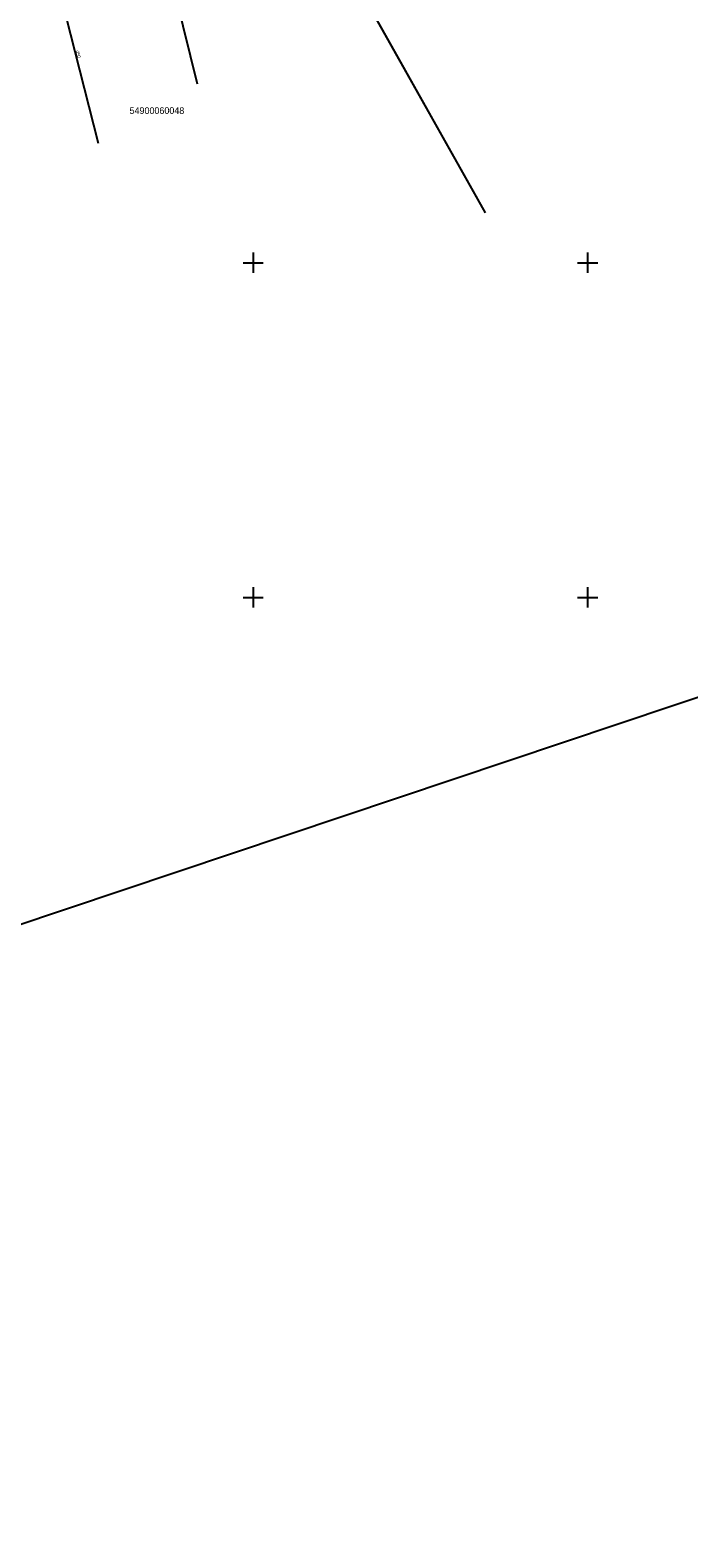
# Model space of a CAD drawing. Extents: x 469981 to 472086, y 246785 to 247785.
# Drawn here: x 471366.7 to 471465.1, y 247109.5 to 247334.7 of the extents above; entities that cross this region are included whole.
import ezdxf

# ---------------------------------------------------------------- set-up
doc = ezdxf.new("R2010")
doc.units = 0
for name, color, linetype in [('DREN_VADP_####_####_#', 7, 'Continuous'), ('DREN_VADP_####_TKST_#', 7, 'Continuous'), ('GEOD_ELEM_####_####_#', 7, 'Continuous'), ('RAMI_PLAN_####_TKST_#', 7, 'Continuous'), ('ROBZ_IERR_####_####_#', 7, 'Continuous'), ('ROBZ_UZMR_####_####_#', 7, 'Continuous'), ('ROBZ_UZMR_####_TKST_#', 7, 'Continuous')]:
    doc.layers.add(name, color=color, linetype=linetype)

msp = doc.modelspace()

# ---------------------------------------------------------------- linework, layer by layer
at = {"layer": 'DREN_VADP_####_####_#'}
for points in [[(471391.68, 247326.68), (471384.23, 247356.95)], [(471369.21, 247347.82), (471376.84, 247317.88)]]:
    msp.add_lwpolyline(points, dxfattribs=at)
at = {"layer": 'GEOD_ELEM_####_####_#'}
for p, q in [((471400, 247301.5), (471400, 247300)), ((471450, 247301.5), (471450, 247300)), ((471398.5, 247300), (471400, 247300)), ((471400, 247300), (471400, 247298.5)), ((471400, 247300), (471401.5, 247300)), ((471448.5, 247300), (471450, 247300)), ((471450, 247300), (471450, 247298.5)), ((471450, 247300), (471451.5, 247300)), ((471400, 247251.5), (471400, 247250)), ((471450, 247251.5), (471450, 247250)), ((471398.5, 247250), (471400, 247250)), ((471400, 247250), (471400, 247248.5)), ((471400, 247250), (471401.5, 247250)), ((471448.5, 247250), (471450, 247250)), ((471450, 247250), (471450, 247248.5)), ((471450, 247250), (471451.5, 247250))]:
    msp.add_line(p, q, dxfattribs=at)
at = {"layer": 'RAMI_PLAN_####_TKST_#'}
msp.add_lwpolyline([(471602.97, 247280.79), (471091.91, 247109.48), (470998.16, 247389.19), (471509.21, 247560.49)], close=True, dxfattribs=at)
at = {"layer": 'ROBZ_IERR_####_####_#'}
msp.add_lwpolyline([(471433.79, 247309.12), (471398.35, 247372.09), (471700.01, 247564.12), (471698.29, 247462.94)], dxfattribs=at)
at = {"layer": 'ROBZ_UZMR_####_####_#'}
msp.add_lwpolyline([(471362.43, 247283.43), (471346.74, 247338.48), (471398.35, 247372.09), (471434.71, 247307.47)], dxfattribs=at)

# ---------------------------------------------------------------- texts
at = {"layer": 'DREN_VADP_####_TKST_#'}
msp.add_text('d50', height=0.5, rotation=284.3007, dxfattribs=at).set_placement((471373.49, 247331.65))
at = {"layer": 'ROBZ_UZMR_####_TKST_#'}
msp.add_text('54900060048', height=1, dxfattribs=at).set_placement((471381.54, 247322.22))

doc.saveas('drawing.dxf')
